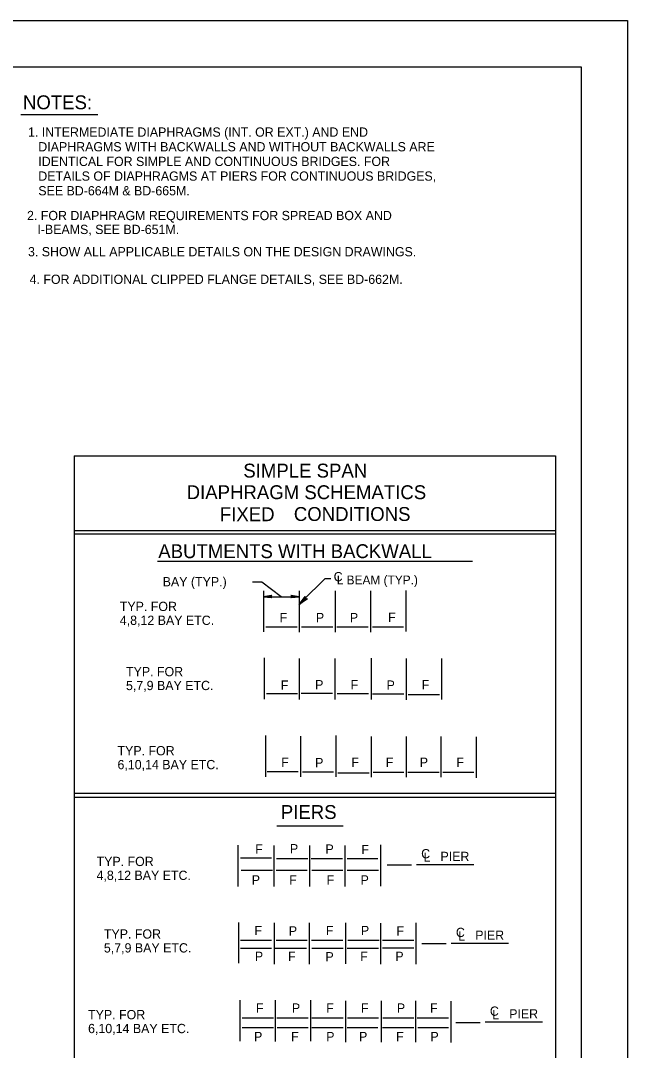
# Model space of a CAD drawing. Extents: x 639028 to 640031, y 298558 to 299746.
# Drawn here: x 639672.4 to 639868.9, y 299412.7 to 299746.3 of the extents above; entities that cross this region are included whole.
import ezdxf

# ---------------------------------------------------------------- set-up
doc = ezdxf.new("R2010")
doc.units = 0
doc.layers.add('1', color=7, linetype='Continuous')
doc.layers.add('PLT-BNDY', color=7, linetype='Continuous')

msp = doc.modelspace()

# ---------------------------------------------------------------- linework, layer by layer
at = {"layer": '1'}
for p, q in [((639067.87, 299731.33), (639853.87, 299731.33)), ((639853.87, 299731.33), (639853.87, 299167.33)), ((639672.39, 299715.86), (639697.38, 299715.86)), ((639689.66, 299605.3), (639689.66, 299340.31)), ((639689.66, 299605.3), (639845.54, 299605.3)), ((639845.54, 299605.3), (639845.54, 299340.31)), ((639689.66, 299581.18), (639845.54, 299581.18)), ((639689.66, 299580.05), (639845.54, 299580.05)), ((639716.68, 299571.18), (639818.76, 299571.18)), ((639771, 299565.55), (639763.63, 299558.3)), ((639771, 299565.55), (639772.88, 299565.55)), ((639747.5, 299564.55), (639750.5, 299564.55)), ((639750.5, 299564.55), (639756.75, 299559.8)), ((639751, 299561.55), (639751, 299548.3)), ((639762.63, 299561.55), (639762.63, 299548.18)), ((639774.25, 299561.55), (639774.25, 299548.18)), ((639785.63, 299561.55), (639785.63, 299548.18)), ((639797.13, 299561.68), (639797.13, 299548.43)), ((639751, 299559.68), (639762.63, 299559.68)), ((639751.75, 299549.93), (639761.88, 299549.93)), ((639763.38, 299549.93), (639773.5, 299549.93)), ((639774.75, 299549.93), (639784.88, 299549.93)), ((639786.38, 299549.93), (639796.38, 299549.93)), ((639751.25, 299539.93), (639751.25, 299526.55)), ((639762.63, 299539.68), (639762.63, 299526.43)), ((639774.13, 299539.68), (639774.13, 299526.43)), ((639785.88, 299539.8), (639785.88, 299526.43)), ((639797.25, 299539.68), (639797.25, 299526.3)), ((639808.63, 299539.68), (639808.63, 299526.43)), ((639752, 299528.3), (639762, 299528.3)), ((639763.25, 299528.43), (639773.38, 299528.43)), ((639774.88, 299528.3), (639785, 299528.3)), ((639786.38, 299528.18), (639796.5, 299528.18)), ((639797.88, 299528.05), (639808, 299528.05)), ((639751.63, 299514.68), (639751.63, 299501.3)), ((639774.5, 299514.68), (639774.5, 299501.3)), ((639763, 299514.55), (639763, 299501.3)), ((639785.88, 299514.43), (639785.88, 299501.18)), ((639797.25, 299514.43), (639797.25, 299501.18)), ((639808.5, 299514.43), (639808.5, 299501.18)), ((639819.88, 299514.3), (639819.88, 299501.05)), ((639752.25, 299503.05), (639762.25, 299503.05)), ((639763.63, 299502.93), (639773.75, 299502.93)), ((639775.13, 299502.68), (639785.25, 299502.68)), ((639786.5, 299502.8), (639796.5, 299502.8)), ((639797.75, 299502.8), (639807.88, 299502.8)), ((639809.13, 299502.8), (639819.13, 299502.8)), ((639689.66, 299496.05), (639845.54, 299496.05)), ((639689.66, 299494.8), (639845.54, 299494.8)), ((639755.38, 299485.43), (639776.85, 299485.43)), ((639742.72, 299479.18), (639742.72, 299465.8)), ((639754.34, 299479.05), (639754.34, 299465.8)), ((639765.97, 299479.05), (639765.97, 299465.8)), ((639777.34, 299479.05), (639777.34, 299465.8)), ((639788.97, 299479.3), (639788.97, 299465.93)), ((639743.59, 299475.05), (639753.59, 299475.05)), ((639755.22, 299474.93), (639765.34, 299474.93)), ((639766.47, 299474.93), (639776.59, 299474.93)), ((639778.09, 299474.93), (639788.09, 299474.93)), ((639791.09, 299472.8), (639798.97, 299472.8)), ((639800.59, 299472.93), (639819.09, 299472.93)), ((639743.84, 299471.05), (639753.97, 299471.05)), ((639755.09, 299471.05), (639765.22, 299471.05)), ((639766.72, 299471.05), (639776.72, 299471.05)), ((639778.09, 299471.05), (639788.22, 299471.05)), ((639742.97, 299454.18), (639742.97, 299440.93)), ((639754.47, 299454.05), (639754.47, 299440.68)), ((639765.84, 299454.05), (639765.84, 299440.68)), ((639777.59, 299454.05), (639777.59, 299440.8)), ((639788.97, 299453.93), (639788.97, 299440.68)), ((639800.34, 299454.05), (639800.34, 299440.68)), ((639743.59, 299448.43), (639753.59, 299448.43)), ((639755.09, 299448.43), (639765.22, 299448.43)), ((639766.59, 299448.43), (639776.72, 299448.43)), ((639778.34, 299448.43), (639788.47, 299448.43)), ((639789.59, 299448.43), (639799.72, 299448.43)), ((639743.59, 299445.8), (639753.59, 299445.8)), ((639754.84, 299445.8), (639764.97, 299445.8)), ((639766.72, 299445.8), (639776.84, 299445.8)), ((639778.09, 299445.8), (639788.22, 299445.8)), ((639789.59, 299445.93), (639799.72, 299445.93)), ((639802.34, 299447.3), (639810.22, 299447.3)), ((639811.84, 299447.43), (639830.34, 299447.43)), ((639743.34, 299428.93), (639743.34, 299415.68)), ((639754.84, 299428.93), (639754.84, 299415.55)), ((639766.22, 299428.93), (639766.22, 299415.68)), ((639777.59, 299428.8), (639777.59, 299415.43)), ((639789.09, 299428.8), (639789.09, 299415.43)), ((639800.22, 299428.8), (639800.22, 299415.43)), ((639811.72, 299428.68), (639811.72, 299415.3)), ((639744.09, 299423.3), (639754.22, 299423.3)), ((639755.34, 299423.3), (639765.47, 299423.3)), ((639766.72, 299423.3), (639776.84, 299423.3)), ((639778.22, 299423.3), (639788.22, 299423.3)), ((639789.72, 299423.3), (639799.72, 299423.3)), ((639800.84, 299423.3), (639810.97, 299423.3)), ((639813.34, 299421.8), (639821.22, 299421.8)), ((639822.84, 299421.93), (639841.34, 299421.93)), ((639744.09, 299420.18), (639754.22, 299420.18)), ((639755.47, 299420.18), (639765.47, 299420.18)), ((639766.72, 299420.18), (639776.84, 299420.18)), ((639778.09, 299420.18), (639788.09, 299420.18)), ((639789.59, 299420.18), (639799.72, 299420.18)), ((639800.97, 299420.18), (639810.97, 299420.18))]:
    msp.add_line(p, q, dxfattribs=at)
for points in [[(639753.63, 299559.43), (639753.5, 299559.55), (639751, 299559.68), (639753.63, 299559.43), (639753.75, 299559.3), (639751, 299559.68), (639753.5, 299559.8), (639753.63, 299560.05), (639751, 299559.68), (639753.75, 299560.18), (639753.63, 299560.05)], [(639760, 299560.05), (639760.13, 299559.8), (639762.63, 299559.68), (639760, 299560.05), (639759.88, 299560.05), (639762.63, 299559.68), (639760.13, 299559.55), (639760, 299559.43), (639762.63, 299559.68), (639759.88, 299559.3), (639760, 299559.43)], [(639765, 299559.05), (639764.75, 299559.18), (639762.63, 299557.18), (639765, 299559.05), (639765.25, 299559.05), (639762.63, 299557.18), (639764.63, 299559.43), (639764.5, 299559.55), (639762.63, 299557.18), (639764.5, 299559.8), (639764.5, 299559.55)]]:
    msp.add_lwpolyline(points, dxfattribs=at)
at = {"layer": 'PLT-BNDY'}
msp.add_lwpolyline([(639027.87, 299746.33), (639868.87, 299746.33), (639868.87, 299152.33), (639027.87, 299152.33)], close=True, dxfattribs=at)

# ---------------------------------------------------------------- texts
at = {"layer": '1'}
for s, height, p in [('NOTES: ', 4.5, (639673.12, 299717.61)), ('1. INTERMEDIATE DIAPHRAGMS (INT. OR EXT.) AND END', 3, (639674.76, 299708.71)), ('   DIAPHRAGMS WITH BACKWALLS AND WITHOUT BACKWALLS ARE', 3, (639674.76, 299703.96)), ('   IDENTICAL FOR SIMPLE AND CONTINUOUS BRIDGES. FOR', 3, (639674.76, 299699.21)), ('   DETAILS OF DIAPHRAGMS AT PIERS FOR CONTINUOUS BRIDGES,', 3, (639674.76, 299694.46)), ('   SEE BD-664M & BD-665M.', 3, (639674.76, 299689.71)), ('2. FOR DIAPHRAGM REQUIREMENTS FOR SPREAD BOX AND', 3, (639674.45, 299681.68)), ('   I-BEAMS, SEE BD-651M.', 3, (639674.45, 299677.18)), ('3. SHOW ALL APPLICABLE DETAILS ON THE DESIGN DRAWINGS.', 3, (639674.76, 299669.96)), ('4. FOR ADDITIONAL CLIPPED FLANGE DETAILS, SEE BD-662M.', 3, (639675.28, 299661.02)), ('SIMPLE SPAN', 4.5, (639744.49, 299598.29)), ('DIAPHRAGM SCHEMATICS', 4.5, (639726.14, 299591.29)), ('FIXED', 4.5, (639736.89, 299584.16)), ('CONDITIONS', 4.5, (639760.85, 299584.23)), ('ABUTMENTS WITH BACKWALL', 4.5, (639716.95, 299572.18)), ('BAY (TYP.)', 3, (639718.38, 299563.05)), ('C', 3, (639773.75, 299564.68)), ('L BEAM (TYP.)', 2.8748, (639774.75, 299563.68)), ('TYP. FOR', 3, (639704.5, 299555.05)), ('4,8,12 BAY ETC.', 3, (639704.5, 299550.55)), ('F', 3, (639756.25, 299551.43)), ('P', 3, (639768, 299551.43)), ('P', 3, (639779, 299551.43)), ('F', 3, (639791.38, 299551.55)), ('TYP. FOR', 3, (639706.5, 299533.93)), ('5,7,9 BAY ETC.', 3, (639706.5, 299529.43)), ('F', 3, (639756.63, 299529.55)), ('P', 3, (639767.75, 299529.68)), ('F', 3, (639779.25, 299529.68)), ('P', 3, (639790.88, 299529.55)), ('F', 3, (639802.25, 299529.68)), ('TYP. FOR', 3, (639703.75, 299508.3)), ('6,10,14 BAY ETC.', 3, (639703.75, 299503.8)), ('F', 3, (639756.75, 299504.55)), ('P', 3, (639767.75, 299504.43)), ('F', 3, (639779.5, 299504.55)), ('F', 3, (639790.63, 299504.55)), ('P', 3, (639801.63, 299504.55)), ('F', 3, (639813.5, 299504.55)), ('PIERS', 4.5, (639756.63, 299487.68)), ('F', 3, (639748.34, 299476.43)), ('P', 3, (639759.59, 299476.55)), ('P', 3, (639771.09, 299476.43)), ('F', 3, (639782.72, 299476.3)), ('C', 3, (639802.09, 299474.93)), ('TYP. FOR', 3, (639696.97, 299472.43)), ('L ', 3, (639802.84, 299473.8)), ('PIER', 3, (639808.34, 299474.05)), ('4,8,12 BAY ETC.', 3, (639696.97, 299467.93)), ('P', 3, (639747.22, 299466.43)), ('F', 3, (639759.34, 299466.43)), ('F', 3, (639771.47, 299466.43)), ('P', 3, (639782.47, 299466.43)), ('TYP. FOR', 3, (639699.34, 299448.93)), ('F', 3, (639748.09, 299450.05)), ('P', 3, (639759.22, 299449.93)), ('F', 3, (639771.22, 299450.05)), ('P', 3, (639782.59, 299450.05)), ('F', 3, (639794.09, 299449.93)), ('C', 3, (639813.34, 299449.43)), ('L ', 3, (639814.09, 299448.3)), ('PIER', 3, (639819.59, 299448.55)), ('5,7,9 BAY ETC.', 3, (639699.34, 299444.43)), ('P', 3, (639748.22, 299441.68)), ('F', 3, (639758.97, 299441.68)), ('P', 3, (639771.09, 299441.55)), ('F', 3, (639782.34, 299441.68)), ('P', 3, (639793.72, 299441.68)), ('F', 3, (639748.59, 299424.93)), ('P', 3, (639760.22, 299424.93)), ('F', 3, (639771.34, 299424.93)), ('F', 3, (639782.59, 299424.93)), ('P', 3, (639794.22, 299424.93)), ('F', 3, (639804.97, 299424.93)), ('TYP. FOR', 3, (639694.22, 299422.8)), ('C', 3, (639824.34, 299423.93)), ('L ', 3, (639825.09, 299422.8)), ('PIER', 3, (639830.59, 299423.05)), ('6,10,14 BAY ETC.', 3, (639694.22, 299418.3)), ('P', 3, (639747.97, 299415.68)), ('F', 3, (639759.97, 299415.68)), ('P', 3, (639771.34, 299415.68)), ('P', 3, (639781.97, 299415.68)), ('F', 3, (639793.97, 299415.68)), ('P', 3, (639805.09, 299415.68))]:
    msp.add_text(s, height=height, dxfattribs=at).set_placement(p)

doc.saveas('drawing.dxf')
